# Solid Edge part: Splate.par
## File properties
Title: Side Plate
Subject: Carrier Assembly
Author: Paul McGrath
Keywords: Side Plate
Comments: Side Plate
Template: metric.par
Last saved by: rkriggs
Revision: 60
Application: Solid Edge
Category: Machined Plate
Manager: Brian Little
Company: Wheels R Us
Density: 9.75436884002e+04 lbm/in^3
Accuracy: 0.00
File Size: 0
Number of Sheets: 0
Number of Objects: 0
Document Number: SP-2070
Revision: 1
Project Name: Trolley Wheel Assembly
Material: 6061-T6 Aluminum
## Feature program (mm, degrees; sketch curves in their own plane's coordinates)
sketch for "unnamed Protrusion 1" plane through (0, 0, 0) normal (0, -1, 0) x-axis (1, 0, 0)
  line (-41.3956, 47.354) -> (78.6044, 47.354)
  line (78.6044, 47.354) -> (78.6044, -2.646)
  line (78.6044, -2.646) -> (43.6044, -132.646)
  line (43.6044, -132.646) -> (-6.3956, -132.646)
  line (-41.3956, -2.646) -> (-6.3956, -132.646)
  line (-41.3956, 47.354) -> (-41.3956, -2.646)
extrude "unnamed Protrusion 1" add finite 15 along -normal
sketch for "unnamed Hole 1" plane through (18.6044, 0, -42.646) normal (0, -1, 0) x-axis (1, 0, 0)
  hole centre (0, -60) bore radius 15
hole "unnamed Hole 1" through
sketch for "Hole_2" plane through (18.6044, 0, -42.646) normal (0, -1, 0) x-axis (1, 0, 0)
  hole centre (30, 65) bore radius 10
hole "Hole_2" through
sketch for "Hole_3" plane through (18.6044, 0, -42.646) normal (0, -1, 0) x-axis (1, 0, 0)
  hole centre (-30, 65) bore radius 10
hole "Hole_3" through
pattern "unnamed Pattern 1" of "Hole_2", "Hole_3"
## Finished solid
Body 1: solid body, 11 faces, 24 edges, 12 vertices.
  Faces by surface: plane 8, cylinder 3
  Edges by curve: line 18, circle 6
Bounding box of the edges (mm): 120.000 x 15.000 x 180.000, from (-41.3956, 0, -132.646) to (78.6044, 15, 47.354).
Cylindrical faces by radius (mm): R10 x2, R15 x1
Planar faces by outward normal: +x 1, +y 1, +z 1, -x 1, -y 1, -z 1, oblique 2
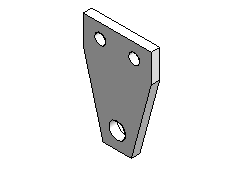
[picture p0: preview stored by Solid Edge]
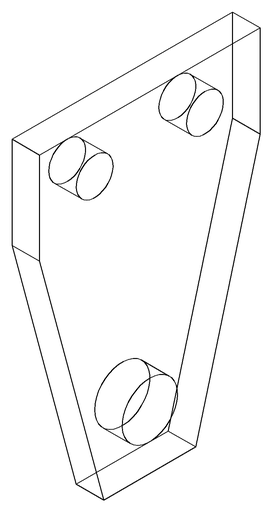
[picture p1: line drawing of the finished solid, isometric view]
